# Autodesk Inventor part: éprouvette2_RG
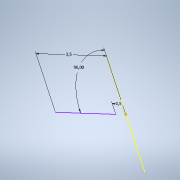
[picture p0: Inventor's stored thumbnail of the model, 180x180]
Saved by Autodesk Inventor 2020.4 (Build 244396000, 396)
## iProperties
Created: 2021-10
Part Number: éprouvette2_RG
Material: Générique
Document SubType Name: Modeling
Designer: mel
Density: 1 g/cm^3
Appearance: Par défaut
Author: mel
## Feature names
1. Balayage1
2. Révolution1 [Revolution]
3. Extrusion1
4. Lissage1
## Parameters: d0 = 0, d1 = 90 deg, d2 = 3.5 mm, d4 = 0.5 mm, d5 = 2 mm, d6 = 0, d7 = 0, d8 = 1 mm, d9 = 2 mm, d10 = 180 deg, d11 = 2 mm, d12 = 1 mm, d13 = 0, d15 = 0.5 mm, d16 = 0.5 mm, d17 = 87 deg, d18 = 87 deg, d19 = 0.5 mm, d20 = 0.5 mm, d21 = 87 deg, d22 = 87 deg, d23 = 0, d24 = 90 deg, d25 = 0, d26 = 90 deg, d27 = 0
